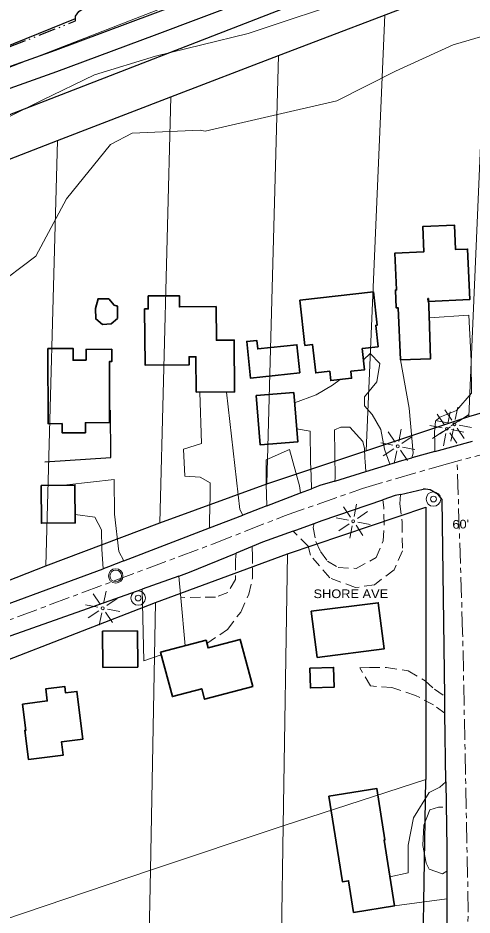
# Model space of a CAD drawing. Extents: x -861682 to -858969, y -1797841 to -1795153.
# Drawn here: x -861295 to -860981, y -1796083 to -1795463 of the extents above; entities that cross this region are included whole.
import ezdxf

# ---------------------------------------------------------------- set-up
doc = ezdxf.new("R2010")
doc.units = 0
doc.header["$LTSCALE"] = 2.4
for name, pattern in [('DASH_DOUBLE_DOT', [9.2, 5, -1.2, 0.3, -1.2, 0.3, -1.2]), ('LONG_DASH_SHORT_DASH', [9.9, 6, -1.2, 1.5, -1.2]), ('MEDIUM_DASHED', [4.5, 3, -1.5])]:
    doc.linetypes.add(name, pattern=pattern)
for name, color, linetype, lineweight in [('10', 7, 'Continuous', 25), ('11', 7, 'Continuous', 13), ('12', 7, 'Continuous', 35), ('14', 7, 'Continuous', 25), ('16', 7, 'DASH_DOUBLE_DOT', 25), ('17', 7, 'Continuous', 13), ('18', 7, 'Continuous', 13), ('30', 7, 'Continuous', 13), ('31', 7, 'Continuous', 13), ('32', 7, 'LONG_DASH_SHORT_DASH', 13), ('36', 7, 'Continuous', 13), ('42', 7, 'Continuous', 25), ('46', 7, 'Continuous', 13), ('6', 7, 'Continuous', 25)]:
    doc.layers.add(name, color=color, linetype=linetype, lineweight=lineweight)
doc.layers.add('43', color=7, linetype='Continuous')

msp = doc.modelspace()

# ---------------------------------------------------------------- linework, layer by layer
at = {"layer": '10'}
for p, q in [((-861007.108, -1795762.792), (-860981.095, -1795755.611)), ((-861007.108, -1795762.792), (-861023.011, -1795767.182)), ((-861054.708, -1795776.631), (-861038.188, -1795771.607)), ((-861076.22, -1795783.173), (-861054.708, -1795776.631)), ((-861123.063, -1795800.359), (-861099.801, -1795791.408)), ((-861099.801, -1795791.408), (-861092.344, -1795788.538)), ((-861030.83, -1795792.349), (-861015.234, -1795788.782)), ((-861123.063, -1795800.359), (-861139.721, -1795806.769)), ((-861104.882, -1795817.708), (-861090.347, -1795812.385)), ((-861133.112, -1795828.373), (-861144.225, -1795832.952)), ((-861183.915, -1795848.869), (-861209.074, -1795857.778)), ((-861303.575, -1795891.243), (-861209.074, -1795857.778)), ((-860999.515, -1795990.939), (-861000.161, -1795943.557)), ((-860998.902, -1796052.768), (-860998.917, -1796071.72)), ((-860998.917, -1796071.72), (-860998.986, -1796161.04))]:
    msp.add_line(p, q, dxfattribs=at)
for points in [[(-861038.188, -1795771.607), (-861029.82, -1795769.062), (-861023.011, -1795767.182)], [(-861076.22, -1795783.173), (-861086.617, -1795786.335), (-861092.344, -1795788.538)], [(-861030.83, -1795792.349), (-861034.572, -1795793.205), (-861042.914, -1795796.053)], [(-861002.175, -1795795.993), (-861004.73, -1795792.428), (-861010.282, -1795789.195), (-861013.542, -1795788.707), (-861015.234, -1795788.782)], [(-861090.347, -1795812.385), (-861084.988, -1795810.423), (-861042.914, -1795796.053)], [(-861000.161, -1795943.557), (-861000.32, -1795931.835), (-861002.175, -1795795.993)], [(-861221.76, -1795838.338), (-861162.582, -1795815.566), (-861139.721, -1795806.769)], [(-861104.882, -1795817.708), (-861125.973, -1795825.431), (-861133.112, -1795828.373)], [(-861183.915, -1795848.869), (-861176.358, -1795846.193), (-861144.225, -1795832.952)], [(-861221.76, -1795838.338), (-861232.393, -1795842.43), (-861236.056, -1795843.783)], [(-861359.875, -1795889.53), (-861358.875, -1795889.14), (-861338.586, -1795881.647), (-861236.056, -1795843.783)], [(-860999.515, -1795990.939), (-860998.89, -1796036.749), (-860998.902, -1796052.768)]]:
    msp.add_lwpolyline(points, dxfattribs=at)
at = {"layer": '11'}
for p, q in [((-861183.915, -1795848.869), (-861182.527, -1795863.79)), ((-861179.443, -1795896.922), (-861182.527, -1795863.79)), ((-861034.967, -1796076.734), (-860998.917, -1796071.72))]:
    msp.add_line(p, q, dxfattribs=at)
for points in [[(-861011.008, -1795670.276), (-860983.677, -1795668.47), (-860981.984, -1795699.882), (-860981.788, -1795722.328), (-860992.079, -1795734.469), (-861003.618, -1795739.06), (-861006.666, -1795741.686), (-861007.307, -1795749.489), (-861007.239, -1795757.286), (-861007.108, -1795762.792)], [(-861056.373, -1795699.415), (-861051.734, -1795695.057), (-861045.058, -1795701.851), (-861047.073, -1795714.629), (-861055.726, -1795724.865), (-861055.671, -1795731.245), (-861050.421, -1795737.106), (-861044.423, -1795747.451), (-861041.941, -1795761.134), (-861038.188, -1795771.607)], [(-861030.902, -1795699.363), (-861024.938, -1795732.866), (-861022.069, -1795763.796), (-861023.011, -1795767.182)], [(-861103.916, -1795729.163), (-861089.056, -1795723.502), (-861077.77, -1795717.024), (-861072.487, -1795713.011)], [(-861169.392, -1795721.84), (-861168.156, -1795757.275), (-861180.646, -1795761.165), (-861179.774, -1795779.824), (-861169.135, -1795780.44), (-861162.248, -1795784.397), (-861162.171, -1795793.139), (-861162.73, -1795810.394), (-861162.582, -1795815.566)], [(-861150.965, -1795721.675), (-861141.765, -1795802.885), (-861139.721, -1795806.769)], [(-861102.512, -1795747.099), (-861093.09, -1795748.585), (-861092.904, -1795769.85), (-861092.583, -1795779.535), (-861092.344, -1795788.538)], [(-861076.22, -1795783.173), (-861076.03, -1795781.044), (-861076.321, -1795747.729), (-861072.082, -1795746.038), (-861065.703, -1795745.982), (-861056.874, -1795755.829), (-861055.649, -1795760.781), (-861055.355, -1795767.395), (-861055.334, -1795769.757), (-861054.708, -1795776.631)], [(-861123.063, -1795800.359), (-861123.49, -1795785.004), (-861123.635, -1795768.464), (-861107.391, -1795761.47), (-861100.557, -1795786.457), (-861099.801, -1795791.408)], [(-861261.244, -1795785.735), (-861228.43, -1795782.14), (-861228.222, -1795806.004), (-861225.161, -1795831.733), (-861221.76, -1795838.338)], [(-861255.393, -1795806.312), (-861241.909, -1795808.014), (-861237.105, -1795816.951), (-861236.99, -1795830.182), (-861236.056, -1795843.783)], [(-861195.952, -1795903.243), (-861207.959, -1795907.434), (-861209.074, -1795857.778)], [(-861038.138, -1796056.727), (-861025.443, -1796053.758), (-861025.608, -1796034.856), (-861021.944, -1796015.891), (-861010.95, -1795998.255), (-861003.621, -1795994.591), (-860999.515, -1795990.939)], [(-861001.501, -1796008.417), (-861004.572, -1796008.443), (-861010.699, -1796010.387), (-861014.625, -1796020.819), (-861015.446, -1796035.003), (-861013.212, -1796047.271), (-861011.051, -1796051.269), (-861001.807, -1796054.496), (-860998.902, -1796052.768)]]:
    msp.add_lwpolyline(points, dxfattribs=at)
at = {"layer": '11', "linetype": 'MEDIUM_DASHED'}
for points in [[(-861030.83, -1795792.349), (-861031.214, -1795798.847), (-861029.685, -1795811.594), (-861029.512, -1795831.441), (-861035.305, -1795844.488), (-861048.684, -1795854.765), (-861061.899, -1795856.771), (-861079.68, -1795850.074), (-861093.05, -1795834.359), (-861094.521, -1795828.228), (-861104.882, -1795817.708)], [(-861090.347, -1795812.385), (-861091.09, -1795815.202), (-861089.352, -1795824.875), (-861085.982, -1795831.935), (-861081.199, -1795838.509), (-861073.835, -1795842.934), (-861061.542, -1795843.536), (-861047.666, -1795836.089), (-861042.805, -1795824.468), (-861042.193, -1795813.357), (-861042.297, -1795801.543), (-861042.914, -1795796.053)], [(-861164.458, -1795895.458), (-861150.257, -1795885.663), (-861141.146, -1795873.768), (-861135.582, -1795861.432), (-861133.08, -1795850.305), (-861132.933, -1795840.143), (-861132.974, -1795835.417), (-861133.112, -1795828.373)], [(-861144.225, -1795832.952), (-861144.769, -1795837.647), (-861144.652, -1795851.115), (-861150.008, -1795860.141), (-861158.487, -1795863.287), (-861168.883, -1795863.377), (-861182.527, -1795863.79)], [(-861000.161, -1795943.557), (-861008.025, -1795937.822), (-861020.369, -1795931.313), (-861036.722, -1795925.785), (-861051.617, -1795924.734), (-861058.815, -1795912.273), (-861052.201, -1795911.979), (-861040.388, -1795911.876), (-861025.479, -1795914.345), (-861013.842, -1795921.096), (-861007.411, -1795926.947), (-861000.32, -1795931.835)]]:
    msp.add_lwpolyline(points, dxfattribs=at)
at = {"layer": '12'}
for points in [[(-861030.902, -1795699.363), (-861010.114, -1795698.709), (-861011.065, -1795668.487), (-861011.087, -1795668.488), (-861011.604, -1795657.124), (-861011.878, -1795657.136), (-861011.795, -1795659.023), (-860982.981, -1795657.756), (-860984.513, -1795622.911), (-860992.812, -1795623.276), (-860993.554, -1795606.396), (-861015.417, -1795607.357), (-861014.651, -1795624.775), (-861034.636, -1795625.654), (-861033.515, -1795651.15), (-861034.395, -1795651.189), (-861033.851, -1795663.457), (-861032.51, -1795663.397)], [(-861171.774, -1795721.861), (-861171.988, -1795697.288), (-861176.714, -1795697.329), (-861176.667, -1795702.764), (-861207.146, -1795703.028), (-861207.482, -1795664.281), (-861204.886, -1795664.258), (-861204.966, -1795655.279), (-861183.463, -1795655.087), (-861183.393, -1795662.889), (-861158.113, -1795662.662), (-861157.905, -1795685.823), (-861145.625, -1795685.713), (-861145.303, -1795721.624)], [(-861100.261, -1795658.145), (-861049.506, -1795652.503), (-861046.945, -1795675.541), (-861047.934, -1795675.651), (-861046.297, -1795690.369), (-861057.244, -1795691.587), (-861055.609, -1795706.282), (-861065.083, -1795707.336), (-861064.55, -1795712.129), (-861079.004, -1795713.736), (-861079.717, -1795707.324), (-861089.375, -1795708.398), (-861091.542, -1795688.914), (-861096.775, -1795689.496)], [(-861241.278, -1795663.868), (-861241.214, -1795671.192), (-861236.456, -1795674.932), (-861230.551, -1795674.644), (-861226.095, -1795670.824), (-861226.169, -1795662.318), (-861228.533, -1795661.574), (-861232.198, -1795657.223), (-861239.527, -1795657.223)], [(-861100.293, -1795708.476), (-861134.288, -1795712.081), (-861136.981, -1795686.688), (-861130.014, -1795685.949), (-861129.383, -1795691.896), (-861102.356, -1795689.029)], [(-861274.354, -1795691.566), (-861274.136, -1795743.549), (-861264.45, -1795743.508), (-861264.423, -1795749.844), (-861248.326, -1795749.775), (-861248.356, -1795742.854), (-861231.616, -1795742.781), (-861231.8, -1795700.638), (-861230.088, -1795700.631), (-861230.123, -1795692.125), (-861247.879, -1795692.198), (-861247.849, -1795699.605), (-861256.792, -1795699.641), (-861256.825, -1795691.496)], [(-861130.403, -1795724.099), (-861127.743, -1795758.102), (-861101.81, -1795756.073), (-861104.471, -1795722.07)], [(-861278.963, -1795786.125), (-861278.734, -1795812.352), (-861255.342, -1795812.148), (-861255.571, -1795785.921)], [(-861088.416, -1795904.969), (-861042.153, -1795899.13), (-861046.179, -1795867.232), (-861092.442, -1795873.071)], [(-861236.494, -1795886.888), (-861236.275, -1795911.934), (-861212.176, -1795911.723), (-861212.396, -1795886.677)], [(-861196.434, -1795901.424), (-861165.079, -1795893.116), (-861163.672, -1795898.427), (-861141.496, -1795892.552), (-861132.855, -1795925.169), (-861166.031, -1795933.958), (-861167.963, -1795926.667), (-861188.315, -1795932.06)], [(-861093.314, -1795912.338), (-861092.958, -1795926.04), (-861076.678, -1795925.617), (-861077.034, -1795911.915)], [(-861291.82, -1795937.23), (-861289.535, -1795955.405), (-861290.191, -1795955.487), (-861287.684, -1795975.542), (-861263.649, -1795972.538), (-861264.804, -1795963.295), (-861250.063, -1795961.453), (-861254.172, -1795928.568), (-861261.972, -1795929.543), (-861262.518, -1795925.174), (-861275.685, -1795926.82), (-861274.652, -1795935.083)], [(-861080.253, -1796000.833), (-861047.218, -1795995.582), (-861041.569, -1796031.122), (-861042.181, -1796031.219), (-861034.974, -1796076.688), (-861063.191, -1796081.161), (-861066.654, -1796059.317), (-861070.876, -1796059.986)]]:
    msp.add_lwpolyline(points, close=True, dxfattribs=at)
at = {"layer": '14'}
for points in [[(-861626.723, -1795630.941), (-861594.952, -1795616.402), (-861472.61, -1795555.55), (-861383.169, -1795515.308), (-861255.076, -1795463.683)], [(-861276.27, -1795769.798), (-861230.691, -1795766.8), (-861230.976, -1795734.194)]]:
    msp.add_lwpolyline(points, dxfattribs=at)
at = {"layer": '16'}
msp.add_lwpolyline([(-861626.723, -1795630.941), (-861472.61, -1795555.55), (-861383.169, -1795515.308), (-861255.062, -1795465.277), (-861255.091, -1795461.969), (-861252.757, -1795458.64), (-861246.18, -1795454.093), (-861224.544, -1795442.326), (-861215.594, -1795438.939), (-861193.906, -1795433.079), (-861174.372, -1795424.165), (-861166.595, -1795421.734), (-861151.552, -1795412.624), (-861140.246, -1795408.508), (-861130.583, -1795405.588), (-861111.007, -1795401.4), (-861092.36, -1795399.11), (-861089.058, -1795398.373), (-861073.286, -1795391.618), (-861053.05, -1795381.754), (-861024.784, -1795371.582), (-861009.693, -1795367.906), (-860990.816, -1795364.905), (-860980.662, -1795364.108)], dxfattribs=at)
at = {"layer": '17'}
for p, q in [((-860995.451, -1795741.034), (-861000.241, -1795733.906)), ((-860998.162, -1795743.691), (-860996.436, -1795735.291)), ((-860992.991, -1795740.574), (-860991.265, -1795732.174)), ((-860996.951, -1795743.234), (-861005.413, -1795741.56)), ((-861000.622, -1795744.151), (-861005.412, -1795737.023)), ((-860995.962, -1795745.091), (-860988.866, -1795740.351)), ((-860990.791, -1795741.974), (-860983.695, -1795737.234)), ((-861034.543, -1795756.263), (-861039.333, -1795749.135)), ((-861032.083, -1795755.803), (-861030.357, -1795747.403)), ((-861002.122, -1795746.351), (-861010.584, -1795744.677)), ((-861001.582, -1795748.851), (-861008.808, -1795753.707)), ((-860996.411, -1795745.734), (-861003.637, -1795750.59)), ((-860996.031, -1795755.694), (-860994.351, -1795747.094)), ((-860995.522, -1795747.611), (-860987.042, -1795749.335)), ((-860991.691, -1795746.634), (-860986.891, -1795753.848)), ((-860990.351, -1795744.494), (-860981.871, -1795746.218)), ((-861029.883, -1795757.203), (-861022.787, -1795752.463)), ((-861001.202, -1795758.811), (-860999.522, -1795750.211)), ((-860996.862, -1795749.751), (-860992.062, -1795756.965)), ((-861036.043, -1795758.463), (-861044.505, -1795756.789)), ((-861035.503, -1795760.963), (-861042.729, -1795765.819)), ((-861029.443, -1795759.723), (-861020.963, -1795761.447)), ((-861035.123, -1795770.923), (-861033.443, -1795762.323)), ((-861030.783, -1795761.863), (-861025.983, -1795769.077)), ((-861065.281, -1795808.044), (-861070.071, -1795800.916)), ((-861062.821, -1795807.584), (-861061.095, -1795799.184)), ((-861060.621, -1795808.984), (-861053.525, -1795804.244)), ((-861066.781, -1795810.244), (-861075.243, -1795808.57)), ((-861066.241, -1795812.744), (-861073.467, -1795817.6)), ((-861065.861, -1795822.704), (-861064.181, -1795814.104)), ((-861061.521, -1795813.644), (-861056.721, -1795820.858)), ((-861060.181, -1795811.504), (-861051.701, -1795813.228)), ((-861235.736, -1795867.696), (-861234.01, -1795859.296)), ((-861238.196, -1795868.156), (-861242.986, -1795861.028)), ((-861233.536, -1795869.096), (-861226.44, -1795864.356)), ((-861239.696, -1795870.356), (-861248.158, -1795868.682)), ((-861239.156, -1795872.856), (-861246.382, -1795877.712)), ((-861233.096, -1795871.616), (-861224.616, -1795873.34)), ((-861238.776, -1795882.816), (-861237.096, -1795874.216)), ((-861234.436, -1795873.756), (-861229.636, -1795880.97))]:
    msp.add_line(p, q, dxfattribs=at)
for centre in [(-860993.651, -1795743.934), (-860998.822, -1795747.051), (-861032.743, -1795759.163), (-861063.481, -1795810.944), (-861236.396, -1795871.056)]:
    msp.add_circle(centre, 1, dxfattribs=at)
at = {"layer": '18'}
for points in [[(-861627.784, -1795676.931), (-861596.674, -1795662.729), (-861531.982, -1795629.555), (-861487.69, -1795614.518), (-861432.082, -1795596.546), (-861364.083, -1795563.344), (-861330.912, -1795546.255), (-861278.234, -1795519.917), (-861241.977, -1795502.494), (-861200.029, -1795489.604), (-861135.894, -1795473.921), (-861059.793, -1795448.445), (-860986.512, -1795424.884), (-860905.443, -1795400.073), (-860827.906, -1795376.712), (-860758.776, -1795364.765), (-860677.115, -1795353.655), (-860512.688, -1795322.681), (-860272.176, -1795291.516), (-860031.805, -1795256.984)], [(-860948.091, -1795468.254), (-860994.524, -1795481.656), (-861034.298, -1795499.962), (-861074.762, -1795520.4), (-861165.551, -1795541.516), (-861169.101, -1795540.839), (-861216.106, -1795542.904), (-861230.925, -1795550.595), (-861261.315, -1795588.195), (-861282.472, -1795627.841), (-861312.053, -1795649.839), (-861374.171, -1795652.981), (-861429.932, -1795653.468), (-861478.083, -1795659.56), (-861515.504, -1795676.664), (-861564.957, -1795696), (-861611.242, -1795726.413), (-861629.124, -1795735.034)]]:
    msp.add_lwpolyline(points, dxfattribs=at)
at = {"layer": '30'}
for p, q in [((-860983.635, -1795738.506), (-860970.492, -1795433.926)), ((-861054.629, -1795762.201), (-861041.637, -1795461.116)), ((-861123.01, -1795785.024), (-861114.992, -1795489.15)), ((-861196.931, -1795812.121), (-861189.32, -1795517.679)), ((-861275.522, -1795841.812), (-861267.618, -1795547.889)), ((-861108.804, -1795833.566), (-861111.76, -1796021.472)), ((-861199.866, -1795867.084), (-861203.476, -1796051.939)), ((-861013.265, -1795989.396), (-861111.76, -1796021.472)), ((-861114.964, -1796204.326), (-861111.76, -1796021.472)), ((-861206.656, -1796231.652), (-861203.476, -1796051.939))]:
    msp.add_line(p, q, dxfattribs=at)
for points in [[(-861626.562, -1795623.983), (-861624.447, -1795622.863), (-860925.467, -1795351.444)], [(-861486.75, -1796148.044), (-861393.277, -1796116.269), (-861203.476, -1796051.939), (-861111.76, -1796021.472)]]:
    msp.add_lwpolyline(points, dxfattribs=at)
at = {"layer": '31'}
for centre, radius in [((-861008.086, -1795795.573), 5), ((-861008.086, -1795795.573), 2), ((-861211.883, -1795863.99), 5), ((-861211.883, -1795863.99), 2)]:
    msp.add_circle(centre, radius, dxfattribs=at)
at = {"layer": '32'}
for points in [[(-861635.972, -1796031.868), (-861610.028, -1796010.347), (-861588.712, -1795995.544), (-861565.619, -1795981.925), (-861538.381, -1795968.898), (-861510.551, -1795957.055), (-861477.984, -1795945.213), (-861420.547, -1795924.488), (-861317.516, -1795885.408), (-861160.601, -1795826.787), (-861110.862, -1795807.247), (-861056.978, -1795788.298), (-861002.502, -1795772.311), (-860944.474, -1795756.916), (-860841.147, -1795735.302), (-860618.21, -1795690.893), (-860377.808, -1795641.449), (-860358.046, -1795636.933), (-860342.059, -1795635.749), (-860328.736, -1795636.637), (-860314.229, -1795638.413), (-860299.425, -1795641.966), (-860286.694, -1795646.999), (-860274.26, -1795653.513)], [(-861016.908, -1797697.112), (-861016.908, -1797629.868), (-861015.071, -1797572.938), (-861015.071, -1797447.139), (-861012.317, -1797374.599), (-861007.726, -1797281.857), (-861003.087, -1797084.148), (-860992.207, -1796696.344), (-860992.984, -1796576.661), (-860989.487, -1796449.983), (-860987.933, -1796343.901), (-860987.544, -1796199.737), (-860984.047, -1796080.831), (-860987.933, -1795887.705), (-860991.735, -1795769.455)]]:
    msp.add_lwpolyline(points, dxfattribs=at)
at = {"layer": '36'}
for radius in [5, 4]:
    msp.add_circle((-861227.375, -1795848.766), radius, dxfattribs=at)
at = {"layer": '42'}
for p, q in [((-861114.992, -1795489.15), (-860970.492, -1795433.926)), ((-861189.32, -1795517.679), (-861114.992, -1795489.15)), ((-861267.618, -1795547.889), (-861189.32, -1795517.679)), ((-861340.778, -1795576.325), (-861267.618, -1795547.889)), ((-860983.635, -1795738.506), (-860899.575, -1795714.591)), ((-861123.01, -1795785.024), (-860983.635, -1795738.506)), ((-861196.931, -1795812.121), (-861123.01, -1795785.024)), ((-861275.522, -1795841.812), (-861196.931, -1795812.121)), ((-861199.866, -1795867.084), (-861108.804, -1795833.566)), ((-861349.51, -1795870.472), (-861275.522, -1795841.812)), ((-861389.894, -1795940.687), (-861199.866, -1795867.084))]:
    msp.add_line(p, q, dxfattribs=at)
for points in [[(-861627.374, -1795659.18), (-861609.983, -1795649.976), (-860911.743, -1795378.903)], [(-861108.804, -1795833.566), (-861013.361, -1795801.305), (-861013.265, -1795989.396)], [(-861114.964, -1796204.326), (-861016.328, -1796173.211), (-861013.265, -1795989.396)]]:
    msp.add_lwpolyline(points, dxfattribs=at)
at = {"layer": '6'}
for points in [[(-861626.979, -1795642.068), (-861544.533, -1795599.421), (-861437.181, -1795553.823), (-861360.226, -1795517.943), (-861269.063, -1795485.483), (-861201.703, -1795460.32), (-861135.053, -1795434.926), (-860930.273, -1795370.755), (-860759.796, -1795329.096), (-860655.328, -1795305.026), (-860586.415, -1795295.208), (-860452.636, -1795272.3), (-860334.137, -1795258.505), (-859981.661, -1795225.976)], [(-861627.338, -1795657.588), (-861543.402, -1795614.17), (-861436.05, -1795568.572), (-861359.095, -1795532.692), (-861267.932, -1795500.232), (-861200.572, -1795475.069), (-861133.922, -1795449.675), (-860929.142, -1795385.504), (-860758.665, -1795343.845), (-860654.197, -1795319.775), (-860585.284, -1795309.957), (-860451.505, -1795287.049), (-860333.006, -1795273.254), (-859980.53, -1795240.725)]]:
    msp.add_lwpolyline(points, dxfattribs=at)

# ---------------------------------------------------------------- texts
at = {"layer": '43', "width": 1.1}
msp.add_text("60'", height=6, rotation=1.892, dxfattribs=at).set_placement((-860994.899, -1795816.153))
at = {"layer": '46', "width": 1.1}
msp.add_text('SHORE AVE', height=6, dxfattribs=at).set_placement((-861090.855, -1795864.039))

doc.saveas('drawing.dxf')
